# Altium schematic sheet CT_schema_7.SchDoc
size 274 x 160 mm
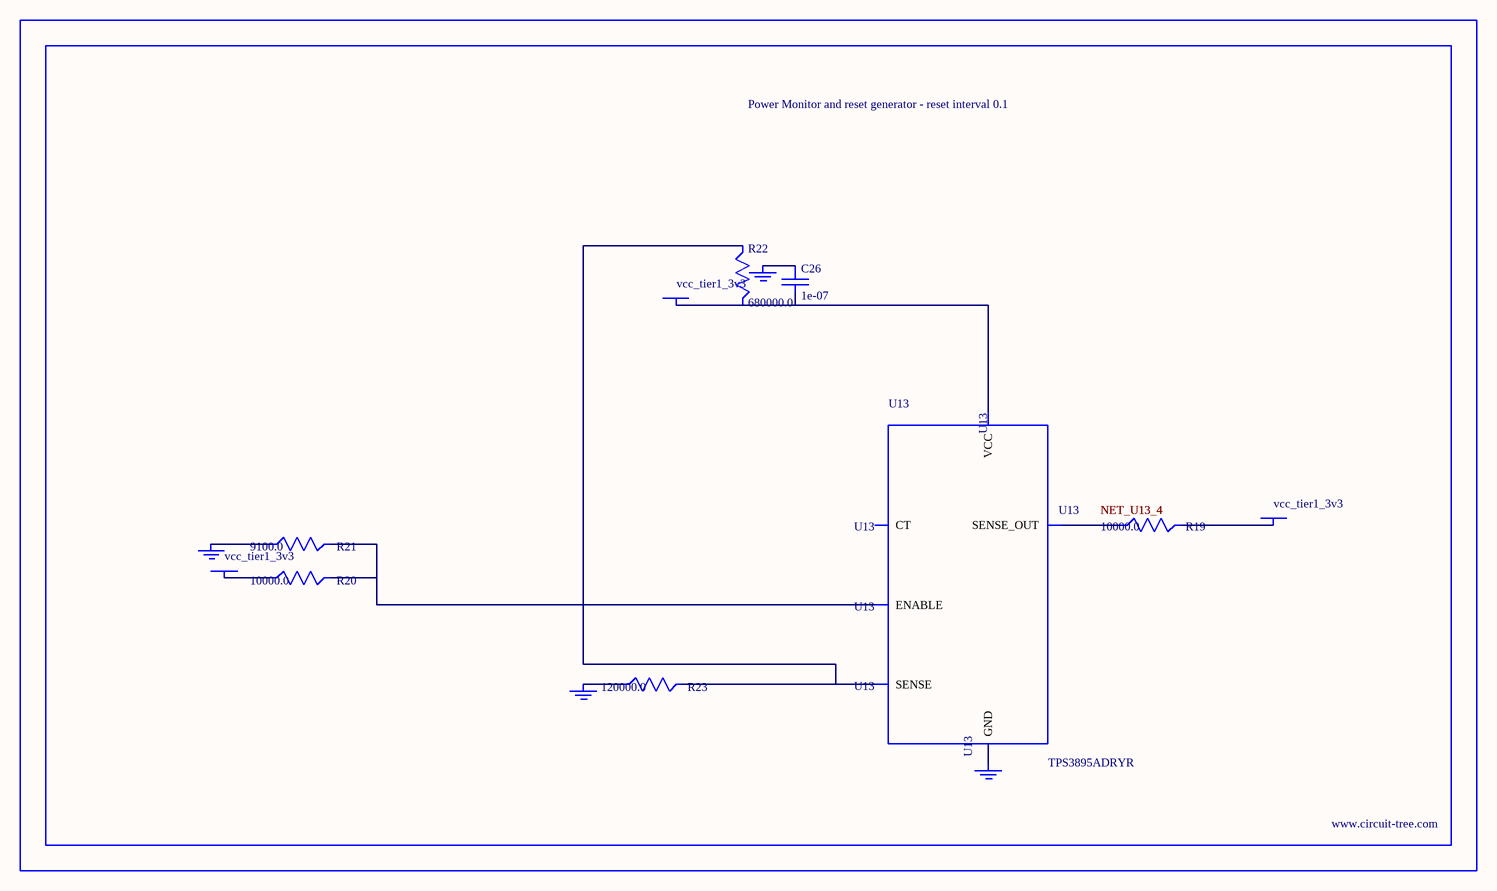
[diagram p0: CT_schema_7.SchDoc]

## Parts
BORDER6  (no value)
C26  1e-07  [C0402]
GND_INSTANCE_6_0  (no value)
GND_INSTANCE_6_1  (no value)
GND_INSTANCE_6_2  (no value)
GND_INSTANCE_6_3  (no value)
POWER_INSTANCE_6_0  vcc_tier1_3v3
POWER_INSTANCE_6_1  vcc_tier1_3v3
POWER_INSTANCE_6_2  vcc_tier1_3v3
R19  10000.0  [R0603]
R20  10000.0  [R0603]
R21  9100.0  [R0603]
R22  680000.0  [R0603]
R23  120000.0  [R0603]
U13  TPS3895ADRYR  [SON-6]

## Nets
NetC26_1: C26.1 GND_INSTANCE_6_2.0(GND)
NetC26_2: C26.2 POWER_INSTANCE_6_2.0(PWR) R22.2 U13.6(VCC)
NetGND_INSTANCE_6_0_0: GND_INSTANCE_6_0.0(GND) R21.1
NetGND_INSTANCE_6_1_0: GND_INSTANCE_6_1.0(GND) R23.1
NetGND_INSTANCE_6_3_0: GND_INSTANCE_6_3.0(GND) U13.2(GND)
NetPOWER_INSTANCE_6_0_0: POWER_INSTANCE_6_0.0(PWR) R20.1
NetPOWER_INSTANCE_6_1_0: POWER_INSTANCE_6_1.0(PWR) R19.2
NetR19_1: R19.1 U13.4(SENSE_OUT)
NetR20_2: R20.2 R21.2 U13.1(ENABLE)
NetR22_1: R22.1 R23.2 U13.3(SENSE)

Not connected (* = marked no-connect by the designer): U13 5(CT)

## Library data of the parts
BORDER6 = BORDER_PAGE6
C26 = C0402C104K3RACTU
GND_INSTANCE_6_0-GND_INSTANCE_6_3 = GND
POWER_INSTANCE_6_0-POWER_INSTANCE_6_2 = PWR
R19 R20 = RC0603JR-0710KL
R21 = RC0603JR-079K1L
R22 = RC0603JR-07680KL
R23 = RC0603JR-07120KL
